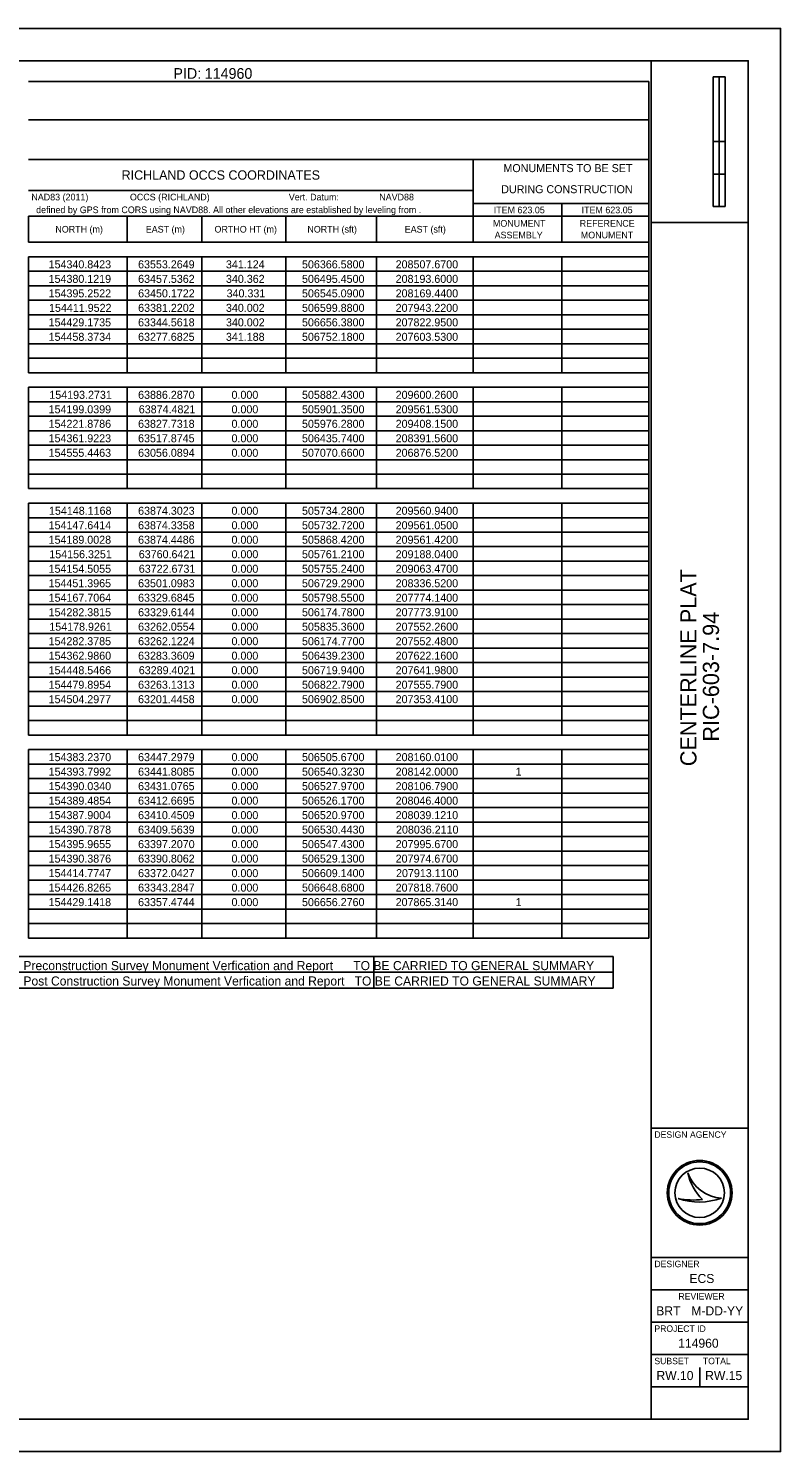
# Model space of a CAD drawing. Extents: x 0 to 680, y 0 to 440.
# Drawn here: x 447.5 to 680, y 0 to 440 of the extents above; entities that cross this region are included whole.
import ezdxf

# ---------------------------------------------------------------- set-up
doc = ezdxf.new("R2010")
doc.units = 0
for name, color, linetype in [('Default', 7, 'Continuous'), ('SH_Border', 7, 'Continuous'), ('SH_Cut_Line', 7, 'Continuous'), ('SH_Data', 7, 'Continuous'), ('SH_Text', 7, 'Continuous')]:
    doc.layers.add(name, color=color, linetype=linetype)

msp = doc.modelspace()

# ---------------------------------------------------------------- linework, layer by layer
at = {"layer": 'Default'}
for p, q in [((554.25, 153.04), (554.25, 143.31)), ((413.79, 148.17), (628.21, 148.17))]:
    msp.add_line(p, q, dxfattribs=at)
msp.add_lwpolyline([(413.79, 153.04), (628.21, 153.04), (628.21, 143.31), (413.79, 143.31)], close=True, dxfattribs=at)
at = {"layer": 'SH_Border'}
for p, q in [((640, 10), (640, 430)), ((640, 380), (670, 380)), ((640, 100), (670, 100)), ((640, 60), (670, 60)), ((640, 50), (670, 50)), ((640, 40), (670, 40)), ((640, 30), (670, 30)), ((640, 20), (670, 20))]:
    msp.add_line(p, q, dxfattribs=at)
msp.add_lwpolyline([(30, 430), (670, 430), (670, 10), (30, 10)], close=True, dxfattribs=at)
at = {"layer": 'SH_Cut_Line'}
msp.add_lwpolyline([(0, 0), (680, 0), (680, 440), (0, 440)], close=True, dxfattribs=at)
at = {"layer": 'SH_Data'}
for p, q in [((659.13, 385), (659.13, 425)), ((662.88, 425), (659.13, 425)), ((659.13, 405), (659.13, 425)), ((659.13, 425), (661, 425)), ((661, 425), (661.02, 425)), ((661.02, 425), (661.02, 405)), ((662.88, 425), (662.88, 385)), ((661.02, 405), (659.13, 405)), ((662.87, 405), (661, 405)), ((661, 405), (661, 395)), ((662.87, 395), (662.87, 405)), ((661, 395), (659.13, 395)), ((659.13, 395), (659.13, 385)), ((661, 395), (662.87, 395)), ((661, 385), (661, 395)), ((662.88, 385), (659.13, 385)), ((659.13, 385), (661, 385)), ((651.35, 86.19), (651.35, 86.19)), ((655, 80), (655, 80)), ((648.34, 78.19), (648.34, 78.19)), ((661.75, 78.37), (661.75, 78.37)), ((655, 20), (655, 26))]:
    msp.add_line(p, q, dxfattribs=at)
for radius in [10, 9.54, 9.54, 7.64]:
    msp.add_circle((655, 80), radius, dxfattribs=at)
for centre, radius, start, end in [((662.32, 89.95), 11.6, 198.9257, 198.9319), ((666.93, 89.4), 15.91, 191.6379, 191.6421), ((662.32, 89.95), 11.6, 198.9319, 267.1657), ((666.93, 89.4), 15.91, 191.6421, 226.0947), ((654.79, 97.4), 20.26, 251.4576, 290.0832), ((652.96, 103.09), 25.32, 259.4964, 259.4995), ((654.79, 97.4), 20.26, 251.4527, 251.4576), ((652.96, 103.09), 25.32, 259.4995, 276.6672)]:
    msp.add_arc(centre, radius, start, end, dxfattribs=at)
at = {"layer": 'SH_Text'}
for p, q in [((447.49, 423.55), (639.3, 423.55)), ((639.3, 423.55), (639.3, 399.53)), ((447.49, 411.72), (639.3, 411.72)), ((447.49, 399.53), (639.3, 399.53)), ((584.98, 399.53), (584.98, 381.96)), ((639.3, 399.53), (639.3, 381.96)), ((447.49, 389.85), (584.98, 389.85)), ((584.98, 385.9), (639.3, 385.9)), ((612.41, 385.9), (612.41, 381.96)), ((447.49, 381.96), (639.3, 381.96)), ((447.49, 381.96), (447.49, 373.89)), ((477.97, 381.96), (477.97, 373.89)), ((501.09, 381.96), (501.09, 373.89)), ((527.08, 381.96), (527.08, 373.89)), ((555.05, 381.96), (555.05, 373.89)), ((584.98, 381.96), (584.98, 373.89)), ((612.41, 381.96), (612.41, 373.89)), ((639.3, 381.96), (639.3, 275.3)), ((447.49, 373.89), (639.3, 373.89)), ((447.49, 369.41), (639.3, 369.41)), ((447.49, 369.41), (447.49, 333.56)), ((477.97, 369.41), (477.97, 333.56)), ((501.09, 369.41), (501.09, 333.56)), ((527.08, 369.41), (527.08, 333.56)), ((555.05, 369.41), (555.05, 333.56)), ((584.98, 369.41), (584.98, 333.56)), ((612.41, 369.41), (612.41, 333.56)), ((447.49, 364.93), (639.3, 364.93)), ((447.49, 360.45), (639.3, 360.45)), ((447.49, 355.97), (639.3, 355.97)), ((447.49, 351.48), (639.3, 351.48)), ((447.49, 347), (639.3, 347)), ((447.49, 342.52), (639.3, 342.52)), ((447.49, 338.04), (639.3, 338.04)), ((447.49, 333.56), (639.3, 333.56)), ((447.49, 329.08), (639.3, 329.08)), ((447.49, 329.08), (447.49, 297.71)), ((477.97, 329.08), (477.97, 297.71)), ((501.09, 329.08), (501.09, 297.71)), ((527.08, 329.08), (527.08, 297.71)), ((555.05, 329.08), (555.05, 297.71)), ((584.98, 329.08), (584.98, 297.71)), ((612.41, 329.08), (612.41, 297.71)), ((447.49, 324.6), (639.3, 324.6)), ((447.49, 320.11), (639.3, 320.11)), ((447.49, 315.63), (639.3, 315.63)), ((447.49, 311.15), (639.3, 311.15)), ((447.49, 306.67), (639.3, 306.67)), ((447.49, 302.19), (639.3, 302.19)), ((447.49, 297.71), (639.3, 297.71)), ((447.49, 293.23), (639.3, 293.23)), ((447.49, 293.23), (447.49, 275.3)), ((477.97, 293.23), (477.97, 275.3)), ((501.09, 293.23), (501.09, 275.3)), ((527.08, 293.23), (527.08, 275.3)), ((555.05, 293.23), (555.05, 275.3)), ((584.98, 293.23), (584.98, 275.3)), ((612.41, 293.23), (612.41, 275.3)), ((447.49, 288.74), (639.3, 288.74)), ((447.49, 284.26), (639.3, 284.26)), ((447.49, 279.78), (639.3, 279.78)), ((447.49, 275.3), (639.3, 275.3)), ((447.49, 275.3), (447.49, 221.52)), ((477.97, 275.3), (477.97, 221.52)), ((501.09, 275.3), (501.09, 221.52)), ((527.08, 275.3), (527.08, 221.52)), ((555.05, 275.3), (555.05, 221.52)), ((584.98, 275.3), (584.98, 221.52)), ((612.41, 275.3), (612.41, 221.52)), ((639.3, 275.3), (639.3, 158.78)), ((447.49, 270.82), (639.3, 270.82)), ((447.49, 266.34), (639.3, 266.34)), ((447.49, 261.86), (639.3, 261.86)), ((447.49, 257.37), (639.3, 257.37)), ((447.49, 252.89), (639.3, 252.89)), ((447.49, 248.41), (639.3, 248.41)), ((447.49, 243.93), (639.3, 243.93)), ((447.49, 239.45), (639.3, 239.45)), ((447.49, 234.97), (639.3, 234.97)), ((447.49, 230.49), (639.3, 230.49)), ((447.49, 226), (639.3, 226)), ((447.49, 221.52), (639.3, 221.52)), ((447.49, 217.04), (639.3, 217.04)), ((447.49, 217.04), (447.49, 158.78)), ((477.97, 217.04), (477.97, 158.78)), ((501.09, 217.04), (501.09, 158.78)), ((527.08, 217.04), (527.08, 158.78)), ((555.05, 217.04), (555.05, 158.78)), ((584.98, 217.04), (584.98, 158.78)), ((612.41, 217.04), (612.41, 158.78)), ((447.49, 212.56), (639.3, 212.56)), ((447.49, 208.08), (639.3, 208.08)), ((447.49, 203.6), (639.3, 203.6)), ((447.49, 199.11), (639.3, 199.11)), ((447.49, 194.63), (639.3, 194.63)), ((447.49, 190.15), (639.3, 190.15)), ((447.49, 185.67), (639.3, 185.67)), ((447.49, 181.19), (639.3, 181.19)), ((447.49, 176.71), (639.3, 176.71)), ((447.49, 172.23), (639.3, 172.23)), ((447.49, 167.74), (639.3, 167.74)), ((447.49, 163.26), (639.3, 163.26)), ((447.49, 158.78), (639.3, 158.78))]:
    msp.add_line(p, q, dxfattribs=at)

# ---------------------------------------------------------------- texts
at = {"layer": 'Default'}
for s, p in [('623   Lump Sum   Preconstruction Survey Monument Verfication and Report      TO BE CARRIED TO GENERAL SUMMARY', (415.33, 148.85)), ('623   Lump Sum   Post Construction Survey Monument Verfication and Report   TO BE CARRIED TO GENERAL SUMMARY', (415.33, 144.09))]:
    msp.add_text(s, height=2.79999, dxfattribs=at).set_placement(p)
at = {"layer": 'SH_Data'}
for s, p in [('CENTERLINE PLAT', (654.02, 211.9)), ('RIC-603-7.94', (660.98, 219.5))]:
    msp.add_text(s, height=5, rotation=90, dxfattribs=at).set_placement(p)
for s, height, p in [('DESIGN AGENCY', 2, (641, 97)), ('DESIGNER', 2, (641, 57)), ('ECS', 2.8, (651.84, 52.1)), ('REVIEWER', 2, (648.44, 47)), ('BRT', 2.8, (641.57, 42.1)), ('M-DD-YY', 2.8, (652.43, 42.1)), ('PROJECT ID', 2, (641, 37)), ('114960', 2.8, (648.37, 32.1)), ('SUBSET', 2, (641, 27)), ('TOTAL', 2, (656, 27)), ('RW.10', 2.8, (641.64, 22.1)), ('RW.15', 2.8, (656.7, 22.1))]:
    msp.add_text(s, height=height, dxfattribs=at).set_placement(p)
at = {"layer": 'SH_Text'}
for s, height, p in [('PID:', 3.298, (492.31, 424.44)), ('114960', 3.298, (501.99, 424.44)), ('RICHLAND OCCS COORDINATES', 2.8861, (476.3, 393.24)), ('  MONUMENTS TO BE SET', 2.4738, (592.5, 395.58)), ('NAD83 (2011)', 2.0615, (448.39, 386.84)), ('OCCS (RICHLAND)', 2.0615, (478.86, 386.84)), ('Vert. Datum:', 2.0615, (527.98, 386.84)), ('NAVD88', 2.061, (555.94, 386.84)), (' DURING CONSTRUCTION', 2.4738, (592.74, 389.06)), (' defined by GPS from CORS using NAVD88. All other elevations are established by leveling from .', 2.0615, (449.1, 382.9)), ('ITEM 623.05', 2.0615, (591.33, 382.85)), ('ITEM 623.05', 2.0615, (618.49, 382.85)), ('NORTH (m)', 2.061, (455.81, 376.89)), ('EAST (m)', 2.061, (483.76, 376.89)), ('ORTHO HT (m)', 2.0615, (505.01, 376.89)), ('NORTH (sft)', 2.0615, (533.72, 376.89)), ('EAST (sft)', 2.061, (563.82, 376.89)), ('MONUMENT ', 2.061, (591.09, 378.7)), ('REFERENCE ', 2.061, (617.92, 378.7)), ('ASSEMBLY', 2.061, (591.61, 375.09)), ('MONUMENT', 2.061, (618.25, 375.09)), ('154340.8423', 2.4738, (453.72, 365.83)), ('63553.2649', 2.474, (481.38, 365.83)), ('341.124', 2.474, (508.54, 365.83)), ('506366.5800', 2.4738, (532.06, 365.83)), ('208507.6700', 2.4738, (561.01, 365.83)), ('154380.1219', 2.4738, (453.72, 361.34)), ('63457.5362', 2.474, (481.4, 361.34)), ('340.362', 2.474, (508.55, 361.34)), ('506495.4500', 2.4738, (532.06, 361.34)), ('208193.6000', 2.4738, (561.01, 361.34)), ('154395.2522', 2.4738, (453.73, 356.86)), ('63450.1722', 2.474, (481.4, 356.86)), ('340.331', 2.474, (508.75, 356.86)), ('506545.0900', 2.4738, (532.06, 356.86)), ('208169.4400', 2.4738, (561.01, 356.86)), ('154411.9522', 2.4738, (453.85, 352.38)), ('63381.2202', 2.474, (481.4, 352.38)), ('340.002', 2.474, (508.55, 352.38)), ('506599.8800', 2.4738, (532.06, 352.38)), ('207943.2200', 2.4738, (561.01, 352.38)), ('154429.1735', 2.4738, (453.71, 347.9)), ('63344.5618', 2.474, (481.38, 347.9)), ('340.002', 2.474, (508.55, 347.9)), ('506656.3800', 2.4738, (532.06, 347.9)), ('207822.9500', 2.4738, (561.01, 347.9)), ('154458.3734', 2.4738, (453.73, 343.42)), ('63277.6825', 2.474, (481.38, 343.42)), ('341.188', 2.474, (508.54, 343.42)), ('506752.1800', 2.4738, (532.06, 343.42)), ('207603.5300', 2.4738, (561.01, 343.42)), ('154193.2731', 2.4738, (453.94, 325.49)), ('63886.2870', 2.474, (481.39, 325.49)), ('0.000', 2.474, (510.27, 325.49)), ('505882.4300', 2.4738, (532.06, 325.49)), ('209600.2600', 2.4738, (561.01, 325.49)), ('154199.0399', 2.4738, (453.72, 321.01)), ('63874.4821', 2.474, (481.6, 321.01)), ('0.000', 2.474, (510.27, 321.01)), ('505901.3500', 2.4738, (532.06, 321.01)), ('209561.5300', 2.4738, (561.01, 321.01)), ('154221.8786', 2.4738, (453.72, 316.53)), ('63827.7318', 2.474, (481.38, 316.53)), ('0.000', 2.474, (510.27, 316.53)), ('505976.2800', 2.4738, (532.06, 316.53)), ('209408.1500', 2.4738, (561.01, 316.53)), ('154361.9223', 2.4738, (453.72, 312.05)), ('63517.8745', 2.474, (481.38, 312.05)), ('0.000', 2.474, (510.27, 312.05)), ('506435.7400', 2.4738, (532.06, 312.05)), ('208391.5600', 2.4738, (561.01, 312.05)), ('154555.4463', 2.4738, (453.72, 307.57)), ('63056.0894', 2.474, (481.39, 307.57)), ('0.000', 2.474, (510.27, 307.57)), ('507070.6600', 2.4738, (532.06, 307.57)), ('206876.5200', 2.4738, (561.01, 307.57)), ('154148.1168', 2.4738, (453.84, 289.64)), ('63874.3023', 2.474, (481.39, 289.64)), ('0.000', 2.474, (510.27, 289.64)), ('505734.2800', 2.4738, (532.06, 289.64)), ('209560.9400', 2.4738, (561.01, 289.64)), ('154147.6414', 2.4738, (453.73, 285.16)), ('63874.3358', 2.474, (481.38, 285.16)), ('0.000', 2.474, (510.27, 285.16)), ('505732.7200', 2.4738, (532.06, 285.16)), ('209561.0500', 2.4738, (561.01, 285.16)), ('154189.0028', 2.4738, (453.72, 280.68)), ('63874.4486', 2.474, (481.39, 280.68)), ('0.000', 2.474, (510.27, 280.68)), ('505868.4200', 2.4738, (532.06, 280.68)), ('209561.4200', 2.4738, (561.01, 280.68)), ('154156.3251', 2.4738, (453.94, 276.2)), ('63760.6421', 2.474, (481.6, 276.2)), ('0.000', 2.474, (510.27, 276.2)), ('505761.2100', 2.4738, (532.06, 276.2)), ('209188.0400', 2.4738, (561.01, 276.2)), ('154154.5055', 2.4738, (453.71, 271.71)), ('63722.6731', 2.474, (481.6, 271.71)), ('0.000', 2.474, (510.27, 271.71)), ('505755.2400', 2.4738, (532.06, 271.71)), ('209063.4700', 2.4738, (561.01, 271.71)), ('154451.3965', 2.4738, (453.71, 267.23)), ('63501.0983', 2.474, (481.39, 267.23)), ('0.000', 2.474, (510.27, 267.23)), ('506729.2900', 2.4738, (532.06, 267.23)), ('208336.5200', 2.4738, (561.01, 267.23)), ('154167.7064', 2.4738, (453.73, 262.75)), ('63329.6845', 2.474, (481.38, 262.75)), ('0.000', 2.474, (510.27, 262.75)), ('505798.5500', 2.4738, (532.06, 262.75)), ('207774.1400', 2.4738, (561.01, 262.75)), ('154282.3815', 2.4738, (453.71, 258.27)), ('63329.6144', 2.474, (481.39, 258.27)), ('0.000', 2.474, (510.27, 258.27)), ('506174.7800', 2.4738, (532.06, 258.27)), ('207773.9100', 2.4738, (561.01, 258.27)), ('154178.9261', 2.4738, (453.94, 253.79)), ('63262.0554', 2.474, (481.39, 253.79)), ('0.000', 2.474, (510.27, 253.79)), ('505835.3600', 2.4738, (532.06, 253.79)), ('207552.2600', 2.4738, (561.01, 253.79)), ('154282.3785', 2.4738, (453.71, 249.31)), ('63262.1224', 2.474, (481.39, 249.31)), ('0.000', 2.474, (510.27, 249.31)), ('506174.7700', 2.4738, (532.06, 249.31)), ('207552.4800', 2.4738, (561.01, 249.31)), ('154362.9860', 2.4738, (453.73, 244.83)), ('63283.3609', 2.474, (481.38, 244.83)), ('0.000', 2.474, (510.27, 244.83)), ('506439.2300', 2.4738, (532.06, 244.83)), ('207622.1600', 2.4738, (561.01, 244.83)), ('154448.5466', 2.4738, (453.72, 240.34)), ('63289.4021', 2.474, (481.6, 240.34)), ('0.000', 2.474, (510.27, 240.34)), ('506719.9400', 2.4738, (532.06, 240.34)), ('207641.9800', 2.4738, (561.01, 240.34)), ('154479.8954', 2.4738, (453.73, 235.86)), ('63263.1313', 2.474, (481.39, 235.86)), ('0.000', 2.474, (510.27, 235.86)), ('506822.7900', 2.4738, (532.06, 235.86)), ('207555.7900', 2.4738, (561.01, 235.86)), ('154504.2977', 2.4738, (453.72, 231.38)), ('63201.4458', 2.474, (481.38, 231.38)), ('0.000', 2.474, (510.27, 231.38)), ('506902.8500', 2.4738, (532.06, 231.38)), ('207353.4100', 2.4738, (561.01, 231.38)), ('154383.2370', 2.4738, (453.73, 213.46)), ('63447.2979', 2.474, (481.38, 213.46)), ('0.000', 2.474, (510.27, 213.46)), ('506505.6700', 2.4738, (532.06, 213.46)), ('208160.0100', 2.4738, (561.01, 213.46)), ('154393.7992', 2.4738, (453.73, 208.97)), ('63441.8085', 2.474, (481.38, 208.97)), ('0.000', 2.474, (510.27, 208.97)), ('506540.3230', 2.4738, (532.06, 208.97)), ('208142.0000', 2.4738, (561.01, 208.97)), ('1', 2.47, (598.12, 208.97)), ('154390.0340', 2.4738, (453.73, 204.49)), ('63431.0765', 2.474, (481.38, 204.49)), ('0.000', 2.474, (510.27, 204.49)), ('506527.9700', 2.4738, (532.06, 204.49)), ('208106.7900', 2.4738, (561.01, 204.49)), ('154389.4854', 2.4738, (453.73, 200.01)), ('63412.6695', 2.474, (481.38, 200.01)), ('0.000', 2.474, (510.27, 200.01)), ('506526.1700', 2.4738, (532.06, 200.01)), ('208046.4000', 2.4738, (561.01, 200.01)), ('154387.9004', 2.4738, (453.73, 195.53)), ('63410.4509', 2.474, (481.38, 195.53)), ('0.000', 2.474, (510.27, 195.53)), ('506520.9700', 2.4738, (532.06, 195.53)), ('208039.1210', 2.4738, (561.01, 195.53)), ('154390.7878', 2.4738, (453.72, 191.05)), ('63409.5639', 2.474, (481.38, 191.05)), ('0.000', 2.474, (510.27, 191.05)), ('506530.4430', 2.4738, (532.06, 191.05)), ('208036.2110', 2.4738, (561.13, 191.05)), ('154395.9655', 2.4738, (453.71, 186.57)), ('63397.2070', 2.474, (481.39, 186.57)), ('0.000', 2.474, (510.27, 186.57)), ('506547.4300', 2.4738, (532.06, 186.57)), ('207995.6700', 2.4738, (561.01, 186.57)), ('154390.3876', 2.4738, (453.72, 182.09)), ('63390.8062', 2.474, (481.4, 182.09)), ('0.000', 2.474, (510.27, 182.09)), ('506529.1300', 2.4738, (532.06, 182.09)), ('207974.6700', 2.4738, (561.01, 182.09)), ('154414.7747', 2.4738, (453.72, 177.6)), ('63372.0427', 2.474, (481.39, 177.6)), ('0.000', 2.474, (510.27, 177.6)), ('506609.1400', 2.4738, (532.06, 177.6)), ('207913.1100', 2.4738, (561.13, 177.6)), ('154426.8265', 2.4738, (453.71, 173.12)), ('63343.2847', 2.474, (481.39, 173.12)), ('0.000', 2.474, (510.27, 173.12)), ('506648.6800', 2.4738, (532.06, 173.12)), ('207818.7600', 2.4738, (561.01, 173.12)), ('154429.1418', 2.4738, (453.72, 168.64)), ('63357.4744', 2.474, (481.39, 168.64)), ('0.000', 2.474, (510.27, 168.64)), ('506656.2760', 2.4738, (532.06, 168.64)), ('207865.3140', 2.4738, (561.01, 168.64)), ('1', 2.47, (598.12, 168.64))]:
    msp.add_text(s, height=height, dxfattribs=at).set_placement(p)

doc.saveas('drawing.dxf')
